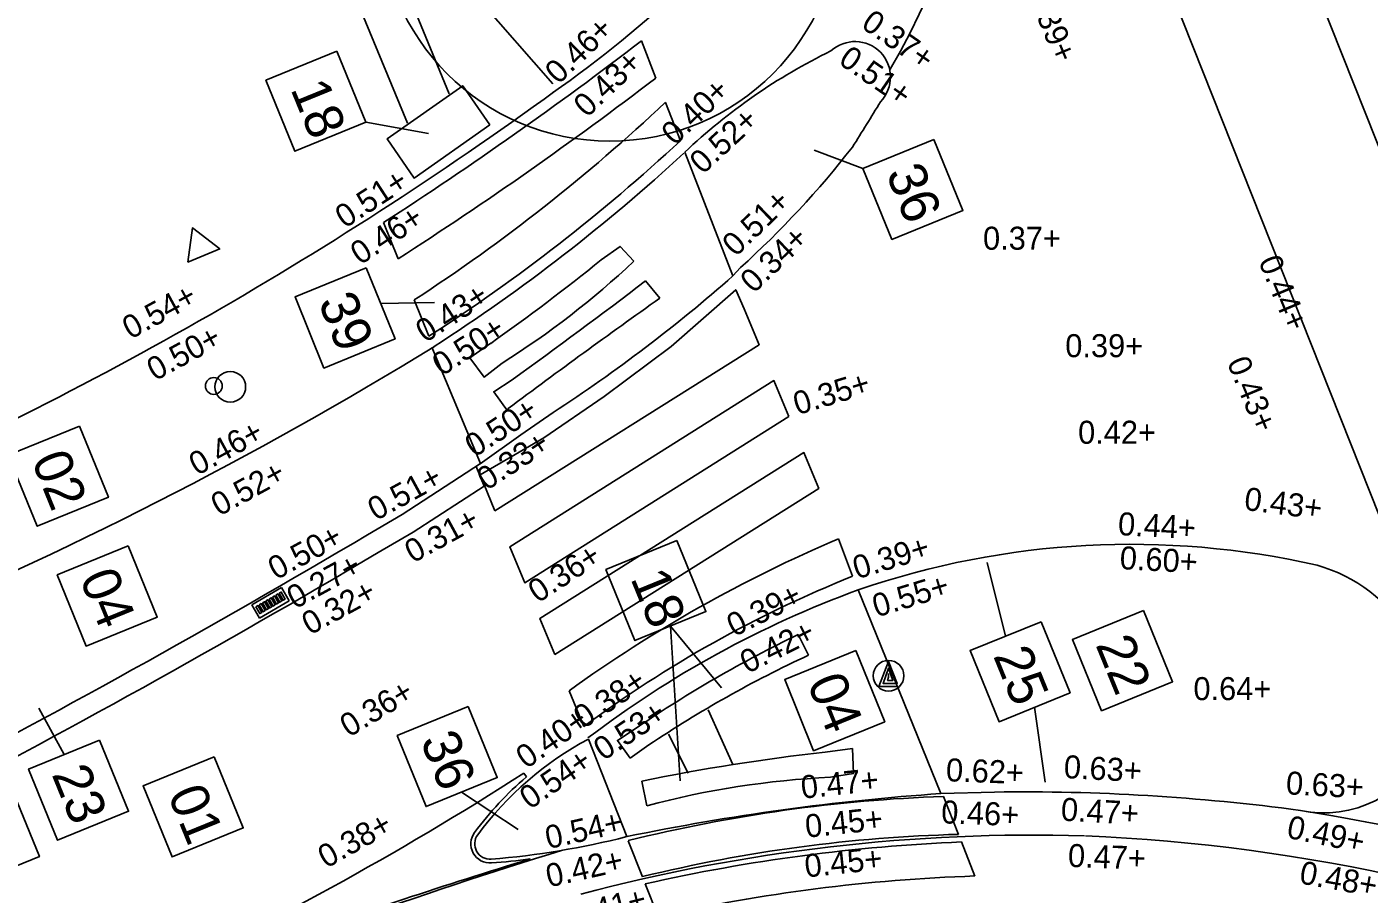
# Model space of a CAD drawing. Extents: x 122462 to 123306, y 485548 to 486417.
# Drawn here: x 122912.13 to 122929.62, y 485817.97 to 485829.27 of the extents above; entities that cross this region are included whole.
import ezdxf

# ---------------------------------------------------------------- set-up
doc = ezdxf.new("R2010")
doc.units = 0
for name, color, linetype in [('B nummers', 7, 'Continuous'), ('B-WE-GR-BOOM-S', 7, 'Continuous'), ('B-WE-OG-HOOGTEPUNT-S', 7, 'Continuous'), ('V bss 4 strekken', 7, 'Continuous'), ('V markering fietsblokken', 7, 'Continuous'), ('V markering figuratie', 7, 'Continuous'), ('V materiaalscheiding algemeen', 7, 'Continuous'), ('V meubilair trammast', 7, 'Continuous'), ('V meubilair verkeersbord', 7, 'Continuous'), ('V Rails', 7, 'Continuous'), ('V riool straatkolk', 7, 'Continuous'), ('V Trottoirband Natuursteen 150', 7, 'Continuous'), ('V Trottoirband Natuursteen 200', 7, 'Continuous'), ('V Trottoirband Natuursteen 200 rond', 7, 'Continuous'), ('V Trottoirband Natuursteen 300', 7, 'Continuous'), ('V Trottoirband Natuursteen overig', 7, 'Continuous'), ('V verwijderen stalen bomrand', 7, 'Continuous')]:
    doc.layers.add(name, color=color, linetype=linetype)

msp = doc.modelspace()

# ---------------------------------------------------------------- linework, layer by layer
at = {"layer": 'B nummers'}
for p, q in [((122916.549, 485828.024), (122917.365, 485827.879)), ((122923.024, 485827.424), (122922.388, 485827.663)), ((122916.739, 485825.664), (122917.44, 485825.677)), ((122924.884, 485821.33), (122924.644, 485822.288)), ((122920.516, 485821.46), (122921.183, 485820.655)), ((122920.516, 485821.46), (122920.645, 485819.446)), ((122912.615, 485819.786), (122912.288, 485820.391)), ((122925.262, 485820.404), (122925.401, 485819.426)), ((122917.796, 485819.298), (122918.533, 485818.809))]:
    msp.add_line(p, q, dxfattribs=at)
for points in [[(122916.171, 485828.95), (122916.549, 485828.024), (122915.623, 485827.646), (122915.245, 485828.572)], [(122923.95, 485827.802), (122924.328, 485826.876), (122923.402, 485826.498), (122923.024, 485827.424)], [(122916.55, 485826.127), (122916.928, 485825.201), (122916.002, 485824.823), (122915.625, 485825.749)], [(122912.814, 485824.065), (122913.192, 485823.139), (122912.266, 485822.762), (122911.888, 485823.688)], [(122913.45, 485822.505), (122913.828, 485821.579), (122912.902, 485821.201), (122912.525, 485822.127)], [(122920.602, 485822.575), (122920.979, 485821.649), (122920.053, 485821.271), (122919.676, 485822.197)], [(122926.682, 485821.662), (122927.06, 485820.736), (122926.134, 485820.359), (122925.756, 485821.284)], [(122925.347, 485821.518), (122925.725, 485820.593), (122924.799, 485820.215), (122924.421, 485821.141)], [(122922.932, 485821.141), (122923.309, 485820.215), (122922.383, 485819.837), (122922.006, 485820.763)], [(122917.882, 485820.413), (122918.259, 485819.487), (122917.333, 485819.109), (122916.956, 485820.035)], [(122913.078, 485819.975), (122913.456, 485819.049), (122912.53, 485818.671), (122912.152, 485819.597)], [(122914.571, 485819.757), (122914.949, 485818.831), (122914.023, 485818.453), (122913.645, 485819.379)], [(122911.915, 485819.384), (122912.293, 485818.458), (122911.367, 485818.08), (122910.989, 485819.006)]]:
    msp.add_lwpolyline(points, close=True, dxfattribs=at)
at = {"layer": 'B-WE-GR-BOOM-S'}
msp.add_circle((122919.729, 485830.778), 3, dxfattribs=at)
at = {"layer": 'V bss 4 strekken'}
msp.add_lwpolyline([(122918.088, 485823.285), (122917.162, 485822.685), (122916.708, 485822.419)], dxfattribs=at)
msp.add_arc((122853.766, 485928.547), 123.389, 294.10001, 300.67146, dxfattribs=at)
at = {"layer": 'V markering fietsblokken'}
for p, q in [((122932.852, 485819.883), (122928.431, 485831.017)), ((122931.208, 485819.234), (122926.787, 485830.368))]:
    msp.add_line(p, q, dxfattribs=at)
at = {"layer": 'V markering figuratie'}
for p, q in [((122920.328, 485828.601), (122920.139, 485829.086)), ((122920.647, 485827.782), (122920.451, 485828.284)), ((122916.967, 485826.245), (122916.779, 485826.718)), ((122917.368, 485825.236), (122917.179, 485825.71)), ((122924.269, 485818.747), (122924.073, 485819.242)), ((122924.485, 485818.205), (122924.309, 485818.649))]:
    msp.add_line(p, q, dxfattribs=at)
for points in [[(122918.23, 485822.963), (122921.671, 485825.127), (122921.476, 485825.595), (122921.367, 485825.842), (122920.526, 485825.103), (122919.652, 485824.453), (122918.868, 485823.915), (122918.035, 485823.431)], [(122922.06, 485824.19), (122918.619, 485822.026), (122918.425, 485822.495), (122921.866, 485824.659)], [(122919.009, 485821.09), (122922.45, 485823.254), (122922.255, 485823.722), (122918.814, 485821.558)]]:
    msp.add_lwpolyline(points, close=True, dxfattribs=at)
for points in [[(122922.708, 485822.598), (122922.891, 485822.11)], [(122919.389, 485820.152), (122919.195, 485820.619)], [(122918.608, 485819.546), (122918.64, 485819.497)], [(122919.965, 485818.665), (122920.152, 485818.196)], [(122920.189, 485818.103), (122920.357, 485817.679)]]:
    msp.add_lwpolyline(points, dxfattribs=at)
for centre, radius in [((122914.781, 485824.578), 0.2), ((122914.566, 485824.589), 0.11)]:
    msp.add_circle(centre, radius, dxfattribs=at)
for centre, radius, start, end in [((122889.885, 485868.455), 49.651, 302.7969, 307.5416), ((122889.885, 485868.455), 50.151, 302.6844, 307.3749), ((122904.467, 485845.231), 23.295, 303.0723, 313.3256), ((122904.467, 485845.231), 23.795, 302.8293, 312.8387), ((122929.755, 485805.98), 18.05, 112.978, 125.8042), ((122928.685, 485807.635), 15.591, 111.8173, 126.6026), ((122895.628, 485855.383), 42.572, 294.7894, 302.6691), ((122921.499, 485816.155), 4.398, 130.5563, 143.4796), ((122924.769, 485799.355), 19.899, 92.0033, 103.9689), ((122918.166, 485818.624), 0.25, 143.4796, 274.6134), ((122924.769, 485799.355), 19.399, 91.4747, 103.7693), ((122925.265, 485795.624), 23.045, 92.3794, 102.7262), ((122938.857, 485752.285), 69.149, 106.95744, 109.82381), ((122917.327, 485829.02), 10.68, 274.6134, 277.3294), ((122925.265, 485795.624), 22.595, 91.9796, 102.5466)]:
    msp.add_arc(centre, radius, start, end, dxfattribs=at)
at = {"layer": 'V materiaalscheiding algemeen'}
for points in [[(122917.089, 485828.012), (122915.199, 485832.58), (122915.487, 485839.962), (122916.645, 485844.433), (122916.55, 485845.405)], [(122917.171, 485845.163), (122917.255, 485844.298), (122916.133, 485839.936), (122915.862, 485832.701), (122917.632, 485828.393)], [(122918.162, 485827.99), (122917.81, 485828.5), (122916.824, 485827.807), (122917.176, 485827.297), (122918.162, 485827.99)], [(122920.039, 485826.213), (122919.86, 485826.407), (122919.614, 485826.232)], [(122920.192, 485825.957), (122920.379, 485825.733)], [(122917.903, 485824.956), (122918.176, 485825.145)], [(122917.903, 485824.956), (122918.089, 485824.704), (122918.323, 485824.887)], [(122918.394, 485824.264), (122918.214, 485824.513), (122918.456, 485824.671)], [(122918.394, 485824.264), (122918.402, 485824.295)], [(122917.983, 485823.54), (122918.088, 485823.285)], [(122922.182, 485821.352), (122922.314, 485821.08)], [(122921.33, 485819.657), (122921.008, 485820.369)], [(122919.994, 485819.74), (122919.825, 485819.971), (122920.082, 485820.139)], [(122920.491, 485820.051), (122920.748, 485819.543)], [(122919.994, 485819.74), (122920.236, 485819.912)], [(122922.89, 485819.864), (122922.532, 485819.82)], [(122922.89, 485819.864), (122922.904, 485819.542), (122922.602, 485819.491)], [(122920.209, 485819.12), (122920.144, 485819.441)]]:
    msp.add_lwpolyline(points, dxfattribs=at)
for centre, radius, start, end in [((122913.526, 485834.345), 11.35, 330.263, 13.5485), ((122901.402, 485848.83), 29.024, 305.3065, 308.8656), ((122912.425, 485834.293), 11.102, 302.0892, 313.2993), ((122872.839, 485888.065), 78.101, 305.73794, 307.32292), ((122979.158, 485742.844), 101.615, 125.34159, 126.72005), ((122929.426, 485806.386), 16.627, 115.8293, 124.1938), ((122928.647, 485807.38), 15.093, 114.8102, 123.8686), ((122925.512, 485793.329), 26.658, 96.419, 101.6174), ((122923.122, 485808.231), 11.272, 92.6465, 104.9789), ((122925.283, 485796.787), 22.537, 63.7818, 81.2109), ((122938.128, 485756.533), 64.859, 107.05047, 112.28047)]:
    msp.add_arc(centre, radius, start, end, dxfattribs=at)
at = {"layer": 'V meubilair trammast'}
msp.add_lwpolyline([(122914.228, 485826.203), (122914.644, 485826.374), (122914.288, 485826.649)], close=True, dxfattribs=at)
at = {"layer": 'V meubilair verkeersbord'}
msp.add_lwpolyline([(122923.484, 485820.676), (122923.232, 485820.676), (122923.359, 485820.999), (122923.473, 485820.714), (122923.288, 485820.714), (122923.359, 485820.914), (122923.415, 485820.754), (122923.346, 485820.754), (122923.359, 485820.794), (122923.36, 485820.844)], dxfattribs=at)
msp.add_circle((122923.359, 485820.814), 0.2, dxfattribs=at)
at = {"layer": 'V Rails'}
for centre, radius, start, end in [((122925.265, 485795.624), 23.115, 88.3939, 104.8282), ((122924.907, 485795.009), 23.742, 46.4579, 87.5462)]:
    msp.add_arc(centre, radius, start, end, dxfattribs=at)
at = {"layer": 'V riool straatkolk'}
for p, q in [((122915.45, 485821.962), (122915.06, 485821.737)), ((122915.55, 485821.789), (122915.45, 485821.962)), ((122915.16, 485821.564), (122915.55, 485821.789)), ((122915.06, 485821.737), (122915.16, 485821.564))]:
    msp.add_line(p, q, dxfattribs=at)
for points in [[(122915.157, 485821.738), (122915.184, 485821.754), (122915.236, 485821.664), (122915.209, 485821.648), (122915.157, 485821.738)], [(122915.2, 485821.763), (122915.228, 485821.779), (122915.28, 485821.688), (122915.252, 485821.673), (122915.2, 485821.763)], [(122915.243, 485821.788), (122915.271, 485821.804), (122915.323, 485821.713), (122915.295, 485821.697), (122915.243, 485821.788)], [(122915.286, 485821.813), (122915.314, 485821.829), (122915.366, 485821.738), (122915.339, 485821.722), (122915.286, 485821.813)], [(122915.33, 485821.838), (122915.358, 485821.854), (122915.41, 485821.763), (122915.382, 485821.747), (122915.33, 485821.838)], [(122915.373, 485821.863), (122915.401, 485821.879), (122915.453, 485821.788), (122915.425, 485821.772), (122915.373, 485821.863)], [(122915.416, 485821.888), (122915.444, 485821.904), (122915.496, 485821.813), (122915.469, 485821.797), (122915.416, 485821.888)], [(122915.113, 485821.713), (122915.141, 485821.729), (122915.193, 485821.639), (122915.165, 485821.623), (122915.113, 485821.713)]]:
    msp.add_lwpolyline(points, dxfattribs=at)
at = {"layer": 'V Trottoirband Natuursteen 150'}
for centre, radius, start, end in [((122911.111, 485839.798), 13.844, 304.6396, 323.2945), ((122889.885, 485868.455), 49.501, 293.2433, 306.0415), ((122890.369, 485869.117), 51.672, 292.4294, 301.5945)]:
    msp.add_arc(centre, radius, start, end, dxfattribs=at)
at = {"layer": 'V Trottoirband Natuursteen 200'}
msp.add_arc((122927.607, 485809.278), 13.48, 110.1502, 127.2825, dxfattribs=at)
at = {"layer": 'V Trottoirband Natuursteen 200 rond'}
for points in [[(122924.04, 485819.28), (122922.964, 485821.933)], [(122924.74, 485819.298), (122924.04, 485819.28)]]:
    msp.add_lwpolyline(points, dxfattribs=at)
for centre, radius, start, end in [((122926.518, 485811.583), 10.943, 77.1954, 108.9509), ((122928.399, 485820.304), 2.024, 348.2716, 74.4165), ((122929.033, 485820.509), 1.482, 258.0725, 335.4449), ((122925.121, 485792.287), 27.014, 82.3299, 90.8091)]:
    msp.add_arc(centre, radius, start, end, dxfattribs=at)
at = {"layer": 'V Trottoirband Natuursteen 300'}
for points in [[(122918.041, 485823.577), (122917.409, 485825.095)], [(122918.988, 485824.244), (122918.567, 485823.953), (122918.039, 485823.574)], [(122918.041, 485823.577), (122917.02, 485822.915), (122916.571, 485822.651)]]:
    msp.add_lwpolyline(points, dxfattribs=at)
for centre, radius, start, end in [((122904.467, 485845.231), 23.945, 302.8039, 312.6577), ((122907.936, 485841.239), 20.273, 303.0364, 311.3583), ((122853.769, 485928.556), 123.126, 294.09587, 300.66803), ((122926.19, 485788.399), 30.955, 93.9812, 101.6345)]:
    msp.add_arc(centre, radius, start, end, dxfattribs=at)
at = {"layer": 'V Trottoirband Natuursteen overig'}
for points in [[(122920.704, 485827.635), (122921.331, 485826.023)], [(122921.331, 485826.023), (122921.429, 485826.131)], [(122919.448, 485819.989), (122919.947, 485818.718)]]:
    msp.add_lwpolyline(points, dxfattribs=at)
for centre, radius, start, end in [((122925.924, 485822.13), 7.586, 115.9141, 133.4824), ((122922.922, 485828.614), 0.462, 315.8273, 132.6823), ((122888.091, 485849.697), 41.166, 327.7039, 328.6702), ((122913.319, 485835.125), 12.11, 312.0385, 322.1953), ((122921.499, 485816.155), 4.348, 118.1478, 143.4796), ((122918.166, 485818.624), 0.2, 143.4796, 274.6134), ((122917.327, 485829.02), 10.63, 274.6134, 284.2697)]:
    msp.add_arc(centre, radius, start, end, dxfattribs=at)
at = {"layer": 'V verwijderen stalen bomrand'}
msp.add_lwpolyline([(122918.982, 485828.523), (122918.026, 485829.624)], dxfattribs=at)

# ---------------------------------------------------------------- texts
at = {"layer": 'B nummers'}
for s, p in [('18', (122915.561, 485828.46)), ('36', (122923.32, 485827.36)), ('39', (122915.921, 485825.685)), ('02', (122912.185, 485823.622)), ('04', (122912.812, 485822.085)), ('18', (122919.991, 485822.085)), ('22', (122926.052, 485821.22)), ('25', (122924.718, 485821.076)), ('04', (122922.293, 485820.721)), ('36', (122917.252, 485819.97)), ('23', (122912.449, 485819.532)), ('01', (122913.961, 485819.268))]:
    msp.add_text(s, height=0.5, rotation=292.187, dxfattribs=at).set_placement(p)
at = {"layer": 'B-WE-OG-HOOGTEPUNT-S'}
for s, rotation, p in [('0.39+', 292.5896, (122925.154, 485829.717)), ('0.37+', 325.3487, (122922.987, 485829.265)), ('0.46+', 43.8188, (122919.058, 485828.508)), ('0.51+', 325.3487, (122922.692, 485828.796)), ('0.43+', 43.8188, (122919.431, 485828.075)), ('0.40+', 43.8188, (122920.575, 485827.71)), ('0.52+', 42.6306, (122920.938, 485827.336)), ('0.51+', 33.0707, (122916.274, 485826.635)), ('0.51+', 43.8188, (122921.368, 485826.262)), ('0.46+', 33.0707, (122916.473, 485826.158)), ('0.34+', 43.8188, (122921.603, 485825.785)), ('0.44+', 292.5896, (122928.174, 485826.215)), ('0.54+', 28.5962, (122913.48, 485825.19)), ('0.43+', 33.0707, (122917.323, 485825.144)), ('0.50+', 28.5962, (122913.8, 485824.648)), ('0.50+', 33.0707, (122917.54, 485824.71)), ('0.43+', 292.5896, (122927.764, 485824.897)), ('0.35+', 16.9326, (122922.172, 485824.207)), ('0.50+', 33.0707, (122917.965, 485823.652)), ('0.46+', 28.5962, (122914.349, 485823.415)), ('0.33+', 33.0707, (122918.121, 485823.219)), ('0.52+', 28.5962, (122914.636, 485822.886)), ('0.51+', 28.5962, (122916.678, 485822.827)), ('0.43+', 352.716, (122927.983, 485822.976)), ('0.31+', 28.5962, (122917.16, 485822.275)), ('0.44+', 356.8597, (122926.343, 485822.647)), ('0.50+', 28.5962, (122915.379, 485822.055)), ('0.36+', 33.0707, (122918.789, 485821.753)), ('0.39+', 16.9326, (122922.948, 485822.069)), ('0.60+', 356.8597, (122926.366, 485822.204)), ('0.27+', 28.5962, (122915.624, 485821.676)), ('0.32+', 28.5962, (122915.819, 485821.337)), ('0.39+', 26.5138, (122921.347, 485821.316)), ('0.55+', 16.9326, (122923.203, 485821.572)), ('0.42+', 26.5138, (122921.521, 485820.836)), ('0.38+', 33.7219, (122919.384, 485820.115)), ('0.36+', 30.9771, (122916.327, 485820.005)), ('0.53+', 33.7219, (122919.644, 485819.699)), ('0.40+', 34.7529, (122918.638, 485819.593)), ('0.54+', 34.7529, (122918.685, 485819.063)), ('0.62+', 357.83, (122924.103, 485819.44)), ('0.63+', 356.8597, (122925.637, 485819.482)), ('0.47+', 6.0441, (122922.233, 485819.211)), ('0.63+', 356.8597, (122928.532, 485819.27)), ('0.46+', 357.83, (122924.041, 485818.892)), ('0.47+', 356.8597, (122925.599, 485818.927)), ('0.38+', 29.325, (122916.032, 485818.298)), ('0.54+', 12.6636, (122918.923, 485818.554)), ('0.45+', 6.0441, (122922.288, 485818.703)), ('0.49+', 348.475, (122928.535, 485818.705)), ('0.47+', 357.83, (122925.693, 485818.325)), ('0.42+', 12.6636, (122918.932, 485818.055)), ('0.45+', 6.0441, (122922.281, 485818.185)), ('0.48+', 349.7778, (122928.7, 485818.111)), ('0.41+', 14.1163, (122919.242, 485817.528))]:
    msp.add_text(s, height=0.3, rotation=rotation, dxfattribs=at).set_placement(p)
for s, p in [('0.37+', (122924.59, 485826.364)), ('0.39+', (122925.662, 485824.964)), ('0.42+', (122925.829, 485823.836)), ('0.64+', (122927.332, 485820.496))]:
    msp.add_text(s, height=0.3, dxfattribs=at).set_placement(p)

doc.saveas('drawing.dxf')
